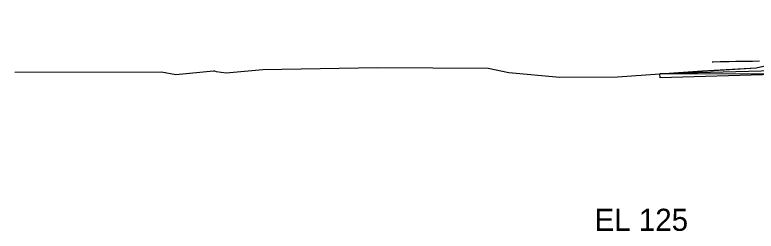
# Model space of a CAD drawing. Extents: x -100 to 4303, y -13 to 10775.
# Drawn here: x -99.5 to -5.5, y 9498.6 to 9526 of the extents above; entities that cross this region are included whole.
import ezdxf

# ---------------------------------------------------------------- set-up
doc = ezdxf.new("R2010")
doc.units = 0
for name, color, linetype in [('CONST_LV3', 7, 'Continuous'), ('DTM_CORRIDOR', 7, 'Continuous'), ('DTM_P_FINISHED_GRADE', 7, 'Continuous'), ('DTM_X_GROUND', 7, 'Continuous'), ('SLOPE_STAKES_FILL', 7, 'Continuous'), ('XS_CELL', 7, 'Continuous'), ('XS_M_SHAPES_EARTHWORK', 7, 'Continuous'), ('XS_P_DR_GRAVEL', 7, 'Continuous'), ('XS_P_GROUND', 7, 'Continuous'), ('XS_X_EXCESS', 7, 'Continuous')]:
    doc.layers.add(name, color=color, linetype=linetype)

msp = doc.modelspace()

# ---------------------------------------------------------------- linework, layer by layer
at = {"layer": 'CONST_LV3'}
msp.add_lwpolyline([(-11.072, 9520.045), (-10.968, 9520.047), (-10.072, 9520.063), (-9.968, 9520.065), (-9.072, 9520.08), (-8.968, 9520.082), (-8.072, 9520.098), (-7.968, 9520.1), (-7.072, 9520.115), (-6.968, 9520.117), (-6.072, 9520.133), (-5.968, 9520.135), (-5.072, 9520.15)], dxfattribs=at)
at = {"layer": 'DTM_P_FINISHED_GRADE'}
msp.add_lwpolyline([(-11.072, 9520.045), (-10.968, 9520.047), (-10.072, 9520.063), (-9.968, 9520.065), (-9.072, 9520.08), (-8.968, 9520.082), (-8.072, 9520.098), (-7.968, 9520.1), (-7.072, 9520.115), (-6.968, 9520.117), (-6.072, 9520.133), (-5.968, 9520.135), (-5.072, 9520.15)], dxfattribs=at)
at = {"layer": 'DTM_X_GROUND'}
msp.add_lwpolyline([(-99.535, 9518.719), (-80.945, 9518.757), (-79.091, 9518.418), (-74.335, 9518.897), (-74.198, 9518.872), (-73.998, 9518.824), (-72.712, 9518.653), (-68.082, 9519.058), (-53.528, 9519.318), (-39.495, 9519.232), (-36.892, 9518.685), (-30.398, 9518.081), (-23.071, 9518.118), (-12.342, 9518.878), (-5.506, 9519.279), (-3.412, 9519.736), (0, 9520.524)], dxfattribs=at)
at = {"layer": 'XS_M_SHAPES_EARTHWORK'}
msp.add_lwpolyline([(87.986, 9518.397), (35.14, 9518.448), (-17.707, 9518.498), (-5.506, 9519.279), (1.92, 9520.967), (8.419, 9523.109), (13.407, 9524.345), (15.631, 9524.625), (18.111, 9525.033), (20.592, 9525.442), (31.847, 9525.912), (41.412, 9525.978), (43.488, 9525.993), (44.527, 9525.833), (45.792, 9525.71), (46.601, 9525.411), (48.238, 9525.433), (50.092, 9525.209), (54.409, 9524.028), (58.726, 9522.847), (62.412, 9522.29), (66.099, 9521.734), (71.648, 9521.239)], close=True, dxfattribs=at)
at = {"layer": 'XS_P_DR_GRAVEL'}
for p, q in [((113.805, 9522.231), (-17.707, 9518.498)), ((113.817, 9521.731), (-17.694, 9517.998)), ((-17.694, 9517.998), (-17.707, 9518.498))]:
    msp.add_line(p, q, dxfattribs=at)
at = {"layer": 'XS_P_GROUND'}
msp.add_line((87.986, 9518.397), (-17.707, 9518.498), dxfattribs=at)
at = {"layer": 'XS_X_EXCESS'}
msp.add_lwpolyline([(87.986, 9518.397), (-17.707, 9518.498), (-5.506, 9519.279), (0, 9520.524), (1.92, 9520.967), (8.419, 9523.109), (13.407, 9524.345), (20.592, 9525.442), (27.71, 9525.74), (36.63, 9525.945), (43.488, 9525.993), (44.527, 9525.833), (45.792, 9525.71), (46.601, 9525.411), (47.42, 9525.422), (48.238, 9525.433), (50.092, 9525.209), (54.409, 9524.028), (58.726, 9522.847), (62.412, 9522.29), (71.648, 9521.239), (79.817, 9519.818)], close=True, dxfattribs=at)

# ---------------------------------------------------------------- texts
at = {"layer": 'DTM_CORRIDOR'}
msp.add_text('X', height=0.001, dxfattribs=at).set_placement((-13.827, 9520.081))
at = {"layer": 'SLOPE_STAKES_FILL'}
msp.add_text('X', height=0.001, dxfattribs=at).set_placement((-13.827, 9520.081))
at = {"layer": 'XS_CELL'}
msp.add_text('EL 125', height=2.8, dxfattribs=at).set_placement((-26, 9498.6))
msp.add_text('EL 125', height=2.8, dxfattribs=at).set_placement((-26, 9498.6))

doc.saveas('drawing.dxf')
